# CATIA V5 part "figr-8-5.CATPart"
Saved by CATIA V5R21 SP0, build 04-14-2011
Part number: Part1
Bounding box of the stored display mesh (mm): x 4.549 to 89.781, y -52.238 to 26.36, z 54 to 147.773
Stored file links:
  D:\CATIA V5R21 E-RESOURCES\CATIA-V5R21\catia-v5r21-prt\c08-catia-v5r20-prt\c08-catia-v5r21-figr-8-5.CATPart
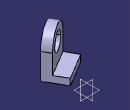
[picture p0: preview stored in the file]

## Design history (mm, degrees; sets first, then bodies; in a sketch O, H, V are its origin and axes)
Body1 (main body)
  Sketch1 on yz-plane, origin (0, 0, 0), H (0, 1, 0), V (0, 0, 1)
    point P1 (-104.4861, 0)
    line L1 (-104.4861, 0) -> (-104.4861, 44.267)
    arc A1 centre (-69.7903, 44.267) radius 34.6958 from (-104.4861, 44.267) to (-35.0946, 44.267) cw
    line L2 (-35.0946, 44.267) -> (-35.0946, 0)
    point P5 (-35.0946, 0)
    line L3 (-35.0946, 0) -> (-104.4861, 0)
    circle A2 centre (-69.7903, 44.267) radius 19.5413
    coincidence: P1 H, P5 H
    vertical: L1 V
    tangency: A1 L1, L2 A1
    horizontal: L3 H
  Pad1: profile Sketch1, direction (1, 0, 0), length 20
  Sketch2 on face of Pad1, origin (0, 0, 0), H (0, -1, 0), V (0, 0, 1)
    point P1 (35.0946, 0)
    line L1 (35.0946, 0) -> (104.4861, 0)
    line L2 (104.4861, 0) -> (104.4861, -15)
    line L3 (104.4861, -15) -> (35.0946, -15)
    line L4 (35.0946, -15) -> (35.0946, 0)
    reference projected line E1 (35.0946, 0) -> (35.0946, 44.267) from edge [face of Pad1 | face of Pad1]
    reference projected line E2 (104.4861, 44.267) -> (104.4861, 0) from edge [face of Pad1 | face of Pad1]
    distance L3 L1 = 15
    coincidence: P1 H, L4 E1, L2 E2
    horizontal: L1 H, L3 H
    vertical: L2 V, L4 V
  Pad2: profile Sketch2, direction (1, 0, 0), length 50
  Translate1: ToTransfor Pad2, Direction xy-plane, Length 69
  Rotate1: ToTransfor Translate1, Axis edge, Angle 121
